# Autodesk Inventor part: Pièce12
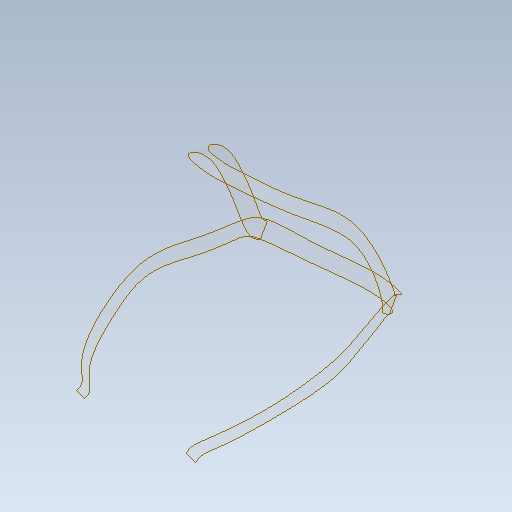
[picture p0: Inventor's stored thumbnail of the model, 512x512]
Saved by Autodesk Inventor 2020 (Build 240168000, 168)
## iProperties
Created: 2021-10
Part Number: Pièce12
Material: Générique
Document SubType Name: Modeling
Designer: bruno
Density: 1 g/cm^3
Appearance: Par défaut
Author: bruno
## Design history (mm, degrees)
feature "Composite1"
body "Srf1"
